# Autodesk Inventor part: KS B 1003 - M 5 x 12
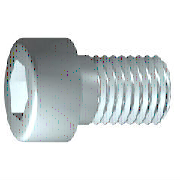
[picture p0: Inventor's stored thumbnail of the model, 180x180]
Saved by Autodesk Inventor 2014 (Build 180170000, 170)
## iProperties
IsCustomPart: 0
Created: 2009-02
Part Number: KS B 1003 - M 5 x 12
Material: 강, 연강
Description: 6각머리 태핑 나사
Document SubType Name: Modeling
Standard: KS B 1003
Designer: KYOUNG IL JANG
Standards Organization: KS
Language: ko-KR
Size Designation: M 5 x 12
Categories: <MemberInstance><Categories><Category DisplayName="조임쇠" InternalName="e4da775c-781d-43d5-af7c-5136215cf5a6" Mnemonic="FSTN"><Category DisplayName="볼트" InternalN
Density: 1 g/cm^3
Appearance: 강철
Author: KYOUNG IL JANG
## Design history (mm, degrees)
sketch "스케치1"
  geometry: L1 (-1.167, 0)-(12, 0); L2 (12, 0)-(12, 2.5); L3 (12, 2.5)-(2, 2.5); L4 (2, 2.5)-(1.509, 2.5); L5 (1.509, 2.5)-(0, 2.5); L6 (0, 2.5)-(0, 4.25); L7 (0, 4.25)-(-5, 4.25); L8 (-5, 4.25)-(-5, 2.309); L9 (-5, 2.309)-(-2.5, 2.309); L10 (-2.5, 2.309)-(-1.167, 0); L11 (-8.4, 0)-(15.4, 0) reference; L12 (0, -0.85)-(0, 5.1) reference; L13 (2, 2.5)-(0, 2.5)
  constraints: 22 end point, 6 parallel, 2 collinear, 2 perpendicular, 1 horizontal, 1 point on line
  dimensions: "d1" = 10 distance from line of L3.end L2 (= GEL); "d2" = 0.49086 distance of L4.end L3.end (computed from GAL); "d3" = 5 distance between parallel lines of L8 L6 (= KOH); "d4" = 2.5 distance of L8.end L9.end (= INTI); "d5" = 60 deg angle of L10 L1; "d6" = 5 diameter of L3 L1 (= GD); "d7" = 5 diameter of L5 L1 (= BDM); "d8" = 4.6188 diameter of L9 L1 (= 1.1547 x SW); "d9" = 8.5 diameter of L7 L1 (= KOD); "d26" = 12 distance between parallel lines of L12 L2 (= NLG)
revolve "본체" sketch "스케치1" stored, may be unused: angle "d10" = 90 deg
sketch "스케치2"
  geometry: L1 (0, -5.95)-(0, 5.95) reference; L2 (-5.95, 0)-(5.95, 0) reference; L3 (2.309, 0)-(1.155, -2); L4 (1.155, -2)-(-1.155, -2); L5 (-1.155, -2)-(-2.309, 0); L6 (-2.309, 0)-(-1.155, 2); L7 (-1.155, 2)-(1.155, 2); L8 (1.155, 2)-(2.309, 0); 2 further points
  constraints: 12 end point, 1 coincident, 1 horizontal alignment, 1 point on line, 12 other
extrude "슬롯" join sketch "스케치2" stored distance "d11" = 10; taper "d12" = 0 deg
workplane "Work Plane1"
fillet "Fillet2" dims "d30" = 0.1 (= R)
body "Solid1"
fillet "모깎기1" dims "d17" = 0.5 (= RR)
feature "스레드" dims "d13" = 10 (= GEL), "d14" = 0
chamfer "모따기1" distance "d15" = 0.49076 (= -0.5 x SPD + 0.5 x GD); stored, may be unused: second distance "d16" = 0.49076 (= GUL), angle "d27" = 45 deg
other parameters: "GD" = 5 (= NND) [user parameter; used in 2 equation terms], "NLG" = 12 [user parameter; used in 1 equation term], "GEL" = 10 [user parameter; used in 2 equation terms], "KOD" = 8.5 [user parameter; used in 1 equation term], "KOH" = 5 [user parameter; used in 1 equation term], "INTI" = 2.5 [user parameter; used in 1 equation term], "GAL" = 0.49076 (= 0.61345 x PTC) [user parameter; used in 1 equation term], "GUL" = 0.49076 (= 0.61345 x PTC) [user parameter; used in 1 equation term], "BDM" = 5 (= NND) [user parameter; used in 1 equation term], "SW" = 4 [user parameter; used in 2 equation terms], "RR" = 0.5 [user parameter; used in 1 equation term], "SPD" = 4.01848 (= NND - 1.2269 x PTC) [user parameter; used in 1 equation term], "d19" = 0, "d28" = 0, "d29" = 0, "R" = 0.1 [user parameter; used in 1 equation term], "PHH" = 0.2 [user parameter], "GD1" = 4.01848 (= THREADDIA - 1.2269 x PTC) [user parameter], "THREADDIA" = 5 [user parameter; used in 1 equation term], "FAWI" = 45 deg [user parameter], "TPU" = 12.5 (computed from PTC) [user parameter], "PTC" = 0.8 [user parameter; used in 5 equation terms], "NND" = 5 [user parameter; used in 3 equation terms], "TOA" = 30 deg [user parameter], "E0" = 4.62 (= 1.155 x SW) [user parameter]
